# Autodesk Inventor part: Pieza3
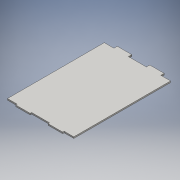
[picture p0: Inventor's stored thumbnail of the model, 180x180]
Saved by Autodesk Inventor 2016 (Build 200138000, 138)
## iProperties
Created: 2016-06
Part Number: Pieza3
Material: Genérico
Document SubType Name: Modeling
Designer: adm
Density: 1 g/cm^3
Appearance: Valor por defecto
Author: adm
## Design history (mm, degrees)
sketch "Boceto1"
  geometry: L1 (-68.5, -100)-(-68.5, 100); L2 (68.5, 100)-(68.5, -100); L3 (68.5, -100)-(-68.5, 100); L4 (-68.5, -100)-(68.5, 100); L5 (-18.5, -100)-(-18.5, -103); L6 (-18.5, -103)-(-48.5, -103); L7 (-48.5, -103)-(-48.5, -100); L8 (18.5, -100)-(18.5, -103); L9 (18.5, -103)-(48.5, -103); L10 (48.5, -103)-(48.5, -100); L11 (-18.5, 100)-(-18.5, 107); L12 (-18.5, 107)-(-48.5, 107); L13 (-48.5, 107)-(-48.5, 100); L14 (18.5, 107)-(48.5, 107); L15 (48.5, 107)-(48.5, 100); L16 (18.5, 100)-(18.5, 107); L17 (48.5, 100)-(68.5, 100); L18 (68.5, -100)-(48.5, -100); L19 (18.5, -100)-(-18.5, -100); L20 (-48.5, -100)-(-68.5, -100); L21 (-68.5, 100)-(-48.5, 100); L22 (-18.5, 100)-(18.5, 100); 1 further point
  constraints: 44 end point, 12 parallel, 3 horizontal, 3 perpendicular, 2 midpoint
  dimensions: "d0" = 200 distance of L2.start L2.end; "d1" = 137 distance of L2.end L1.start; "d2" = 20 distance between parallel lines of L1 L7; "d3" = 30 distance of L5.end L6.end; "d5" = 30 distance between parallel lines of L11 L13; "d6" = 20 distance between parallel lines of L13 L1
extrude "Extrusión1" new body sketch "Boceto1" distance "d8" = 3; taper "d9" = 0 deg
node "Sólido1"
